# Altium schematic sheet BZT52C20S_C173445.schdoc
size 127 x 101 mm
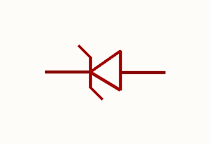
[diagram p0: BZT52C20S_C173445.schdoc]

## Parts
D?  bzt52c20s_c173445  [SOD-323_L1.8-W1.3-LS2.5-RD]  (value not drawn)

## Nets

Not connected (* = marked no-connect by the designer): D? 1 2

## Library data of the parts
D? = bzt52c20s_c173445: 二极管配置:1个独立式;稳压值(标称值):20V;稳压值(范围):18.8V~21.2V;耗散功率(Pd):200mW;; Manufacturer: MDD(辰达半导体); AddInBom: yes; ModelId: db63db13d9e342eb939127d413d6200b; ModelTransform: 104.3305,51.181,0,0,0,0,0,-0.004,0; Diode Configuration: 1个独立式; Zener Voltage(Nom): 20V; Reverse Leakage Current (Ir): 100nA@15V; Pd - Power Dissipation: 200mW; Impedance(Zzt): 50Ω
